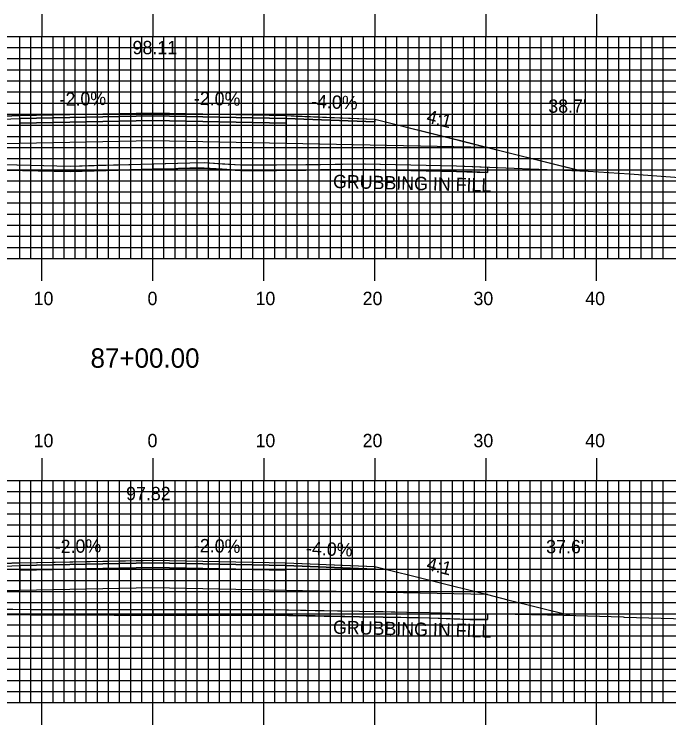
# Model space of a CAD drawing. Extents: x 1763759 to 1764102, y 442591 to 442811.
# Drawn here: x 1763911.8 to 1763970.8, y 442696.7 to 442760.7 of the extents above; entities that cross this region are included whole.
import ezdxf

# ---------------------------------------------------------------- set-up
doc = ezdxf.new("R2010")
doc.units = 0
for name, color, linetype in [('ANNOTATION', 7, 'Continuous'), ('D_Roadway_Centerline', 7, 'Continuous'), ('D_Roadway_Centerline_Text', 7, 'Continuous'), ('D_Roadway_Edge_Shoulder', 7, 'Continuous'), ('D_Roadway_Edge_TW', 7, 'Continuous'), ('D_Roadway_Pavement', 7, 'Continuous'), ('D_Roadway_SlopeLines', 7, 'Continuous'), ('D_Roadway_SubGrade', 7, 'Continuous'), ('D_Text_Standard', 7, 'Continuous'), ('GRUBBING IN FILL', 7, 'Continuous'), ('H_V ANNOTATION', 7, 'Continuous'), ('MAJOR', 7, 'Continuous'), ('MINOR', 7, 'Continuous'), ('S_Roadway_Centerline', 7, 'Continuous')]:
    doc.layers.add(name, color=color, linetype=linetype)

msp = doc.modelspace()

# ---------------------------------------------------------------- linework, layer by layer
at = {"layer": 'D_Roadway_Centerline'}
for points in [[(1763889.187, 442747.431), (1763889.189, 442747.432), (1763890.566, 442747.776), (1763894.144, 442748.67), (1763895.666, 442749.05), (1763904.277, 442751.203), (1763904.318, 442751.213), (1763912.318, 442751.533), (1763924.315, 442751.773), (1763924.318, 442751.773), (1763936.313, 442751.533), (1763936.319, 442751.533), (1763937.226, 442751.497), (1763944.314, 442751.213), (1763944.319, 442751.213), (1763951.794, 442749.345), (1763954.48, 442748.673), (1763954.493, 442748.67), (1763954.495, 442748.67), (1763954.995, 442748.544), (1763956.319, 442748.213), (1763961.352, 442746.955), (1763962.976, 442746.549)], [(1763890.259, 442707.415), (1763894.144, 442708.386), (1763897.914, 442709.329), (1763904.312, 442710.929), (1763904.319, 442710.93), (1763904.324, 442710.93), (1763907.002, 442711.038), (1763912.316, 442711.25), (1763912.319, 442711.25), (1763923.434, 442711.473), (1763924.318, 442711.49), (1763936.316, 442711.25), (1763936.318, 442711.25), (1763944.308, 442710.931), (1763944.319, 442710.93), (1763954.486, 442708.388), (1763954.492, 442708.386), (1763956.316, 442707.931), (1763956.319, 442707.93), (1763961.907, 442706.533), (1763961.911, 442706.532)]]:
    msp.add_lwpolyline(points, dxfattribs=at)
at = {"layer": 'D_Roadway_Edge_Shoulder'}
for points in [[(1763912.318, 442751.533), (1763904.318, 442751.213), (1763904.318, 442750.963), (1763912.318, 442751.283)], [(1763936.319, 442751.533), (1763944.319, 442751.213), (1763944.319, 442750.963), (1763936.319, 442751.283)], [(1763912.319, 442711.25), (1763904.319, 442710.93), (1763904.319, 442710.68), (1763912.319, 442711)], [(1763936.318, 442711.25), (1763944.319, 442710.93), (1763944.319, 442710.68), (1763936.318, 442711)]]:
    msp.add_lwpolyline(points, close=True, dxfattribs=at)
at = {"layer": 'D_Roadway_Edge_TW'}
for points in [[(1763912.318, 442751.283), (1763912.318, 442751.533), (1763924.318, 442751.773), (1763936.319, 442751.533), (1763936.319, 442751.283), (1763924.318, 442751.523)], [(1763936.319, 442751.533), (1763936.319, 442751.533), (1763936.319, 442751.283), (1763936.319, 442751.283)], [(1763912.319, 442711), (1763912.319, 442711.25), (1763924.318, 442711.49), (1763936.318, 442711.25), (1763936.318, 442711), (1763924.318, 442711.24)], [(1763936.318, 442711.25), (1763936.318, 442711.25), (1763936.318, 442711), (1763936.318, 442711)]]:
    msp.add_lwpolyline(points, close=True, dxfattribs=at)
at = {"layer": 'D_Roadway_Pavement'}
for points in [[(1763912.318, 442750.867), (1763912.318, 442751.283), (1763924.318, 442751.523), (1763936.319, 442751.283), (1763936.319, 442750.867), (1763924.318, 442751.107)], [(1763936.319, 442751.283), (1763936.319, 442751.283), (1763936.319, 442750.867), (1763936.319, 442750.867)], [(1763912.319, 442710.583), (1763912.319, 442711), (1763924.318, 442711.24), (1763936.318, 442711), (1763936.318, 442710.583), (1763924.318, 442710.823)], [(1763936.318, 442711), (1763936.318, 442711), (1763936.318, 442710.583), (1763936.318, 442710.583)]]:
    msp.add_lwpolyline(points, close=True, dxfattribs=at)
for points in [[(1763936.319, 442751.283), (1763936.319, 442750.867)], [(1763936.319, 442751.283), (1763936.319, 442750.867)], [(1763936.319, 442751.283), (1763936.319, 442750.867)], [(1763936.318, 442711), (1763936.318, 442710.583)], [(1763936.318, 442711), (1763936.318, 442710.583)], [(1763936.318, 442711), (1763936.318, 442710.583)]]:
    msp.add_lwpolyline(points, dxfattribs=at)
at = {"layer": 'D_Roadway_SlopeLines'}
for points in [[(1763944.319, 442751.213), (1763954.493, 442748.67), (1763956.319, 442748.213), (1763962.976, 442746.549)], [(1763944.319, 442710.93), (1763954.492, 442708.386), (1763956.319, 442707.93), (1763961.911, 442706.532)]]:
    msp.add_lwpolyline(points, dxfattribs=at)
at = {"layer": 'D_Roadway_SubGrade'}
for points in [[(1763904.318, 442750.963), (1763912.318, 442751.283), (1763912.318, 442750.867), (1763912.318, 442749.033), (1763894.144, 442748.67), (1763904.318, 442751.213)], [(1763912.318, 442749.033), (1763912.318, 442750.867), (1763924.318, 442751.107), (1763936.319, 442750.867), (1763936.319, 442749.033), (1763924.318, 442749.273)], [(1763936.319, 442750.867), (1763936.319, 442751.283), (1763944.319, 442750.963), (1763944.319, 442751.213), (1763954.493, 442748.67), (1763936.319, 442749.033)], [(1763936.319, 442750.867), (1763936.319, 442750.867), (1763936.319, 442749.033), (1763936.319, 442749.033)], [(1763904.319, 442710.68), (1763912.319, 442711), (1763912.319, 442710.583), (1763912.319, 442708.75), (1763894.144, 442708.386), (1763904.319, 442710.93)], [(1763912.319, 442708.75), (1763912.319, 442710.583), (1763924.318, 442710.823), (1763936.318, 442710.583), (1763936.318, 442708.75), (1763924.318, 442708.99)], [(1763936.318, 442710.583), (1763936.318, 442711), (1763944.319, 442710.68), (1763944.319, 442710.93), (1763954.492, 442708.386), (1763936.318, 442708.75)], [(1763936.318, 442710.583), (1763936.318, 442710.583), (1763936.318, 442708.75), (1763936.318, 442708.75)]]:
    msp.add_lwpolyline(points, close=True, dxfattribs=at)
at = {"layer": 'GRUBBING IN FILL'}
for p, q in [((1763954.493, 442746.899), (1763954.493, 442746.398)), ((1763954.492, 442706.645), (1763954.492, 442706.145))]:
    msp.add_line(p, q, dxfattribs=at)
for points in [[(1763894.144, 442747.474), (1763896.804, 442747.419), (1763900.618, 442747.34), (1763903.942, 442747.272), (1763906.489, 442747.219), (1763909.661, 442747.153), (1763913.259, 442747.074), (1763916.85, 442746.996), (1763919.345, 442747.064), (1763922.156, 442747.141), (1763924.319, 442747.201), (1763924.319, 442746.7), (1763922.255, 442746.644), (1763916.851, 442746.496), (1763909.658, 442746.653), (1763901.901, 442746.814), (1763894.144, 442746.974)], [(1763894.144, 442747.474), (1763896.804, 442747.419), (1763900.618, 442747.34), (1763903.942, 442747.272), (1763906.489, 442747.219), (1763909.661, 442747.153), (1763913.259, 442747.074), (1763916.85, 442746.996), (1763919.345, 442747.064), (1763922.156, 442747.141), (1763924.319, 442747.201), (1763924.319, 442746.7), (1763922.255, 442746.644), (1763916.851, 442746.496), (1763909.658, 442746.653), (1763901.901, 442746.814), (1763894.144, 442746.974)], [(1763924.319, 442747.201), (1763927.648, 442747.292), (1763928.95, 442747.308), (1763930.586, 442747.199), (1763932.221, 442747.091), (1763935.452, 442747.095), (1763939.424, 442747.138), (1763943.395, 442747.18), (1763947.571, 442747.097), (1763951.694, 442747.014), (1763954.493, 442746.899), (1763954.493, 442746.398), (1763953.085, 442746.456), (1763951.678, 442746.514), (1763947.56, 442746.597), (1763943.442, 442746.68), (1763939.426, 442746.638), (1763933.83, 442746.593), (1763932.205, 442746.591), (1763930.571, 442746.699), (1763928.936, 442746.807), (1763927.658, 442746.792), (1763926.628, 442746.764), (1763926.348, 442746.756), (1763924.319, 442746.7)], [(1763924.319, 442747.201), (1763927.648, 442747.292), (1763928.95, 442747.308), (1763930.586, 442747.199), (1763932.221, 442747.091), (1763935.452, 442747.095), (1763939.424, 442747.138), (1763943.395, 442747.18), (1763947.571, 442747.097), (1763951.694, 442747.014), (1763954.493, 442746.899), (1763954.493, 442746.398), (1763953.085, 442746.456), (1763951.678, 442746.514), (1763947.56, 442746.597), (1763943.442, 442746.68), (1763939.426, 442746.638), (1763933.83, 442746.593), (1763932.205, 442746.591), (1763930.571, 442746.699), (1763928.936, 442746.807), (1763927.658, 442746.792), (1763926.628, 442746.764), (1763926.348, 442746.756), (1763924.319, 442746.7)], [(1763894.144, 442707.484), (1763895.682, 442707.514), (1763899.02, 442707.435), (1763902.359, 442707.356), (1763906.253, 442707.223), (1763911.7, 442707.075), (1763913.254, 442707.06), (1763917.035, 442707.049), (1763920.815, 442707.039), (1763924.319, 442707.036), (1763924.319, 442706.536), (1763920.815, 442706.539), (1763917.035, 442706.549), (1763911.7, 442706.575), (1763906.253, 442706.723), (1763902.359, 442706.856), (1763899.02, 442706.935), (1763895.682, 442707.014), (1763894.144, 442706.984)], [(1763894.144, 442707.484), (1763895.682, 442707.514), (1763899.02, 442707.435), (1763902.359, 442707.356), (1763906.253, 442707.223), (1763911.7, 442707.075), (1763913.254, 442707.06), (1763917.035, 442707.049), (1763920.815, 442707.039), (1763924.319, 442707.036), (1763924.319, 442706.536), (1763920.815, 442706.539), (1763917.035, 442706.549), (1763911.7, 442706.575), (1763906.253, 442706.723), (1763902.359, 442706.856), (1763899.02, 442706.935), (1763895.682, 442707.014), (1763894.144, 442706.984)], [(1763924.319, 442707.036), (1763925.96, 442707.035), (1763931.106, 442707.032), (1763934.963, 442707.032), (1763938.955, 442706.965), (1763942.948, 442706.898), (1763945.078, 442706.86), (1763947.209, 442706.821), (1763949.3, 442706.788), (1763952.904, 442706.644), (1763954.492, 442706.645), (1763954.492, 442706.145), (1763952.904, 442706.144), (1763951.102, 442706.216), (1763948.255, 442706.305), (1763945.078, 442706.36), (1763942.948, 442706.398), (1763938.955, 442706.465), (1763934.963, 442706.532), (1763931.106, 442706.532), (1763925.96, 442706.535), (1763924.319, 442706.536)], [(1763924.319, 442707.036), (1763925.96, 442707.035), (1763931.106, 442707.032), (1763934.963, 442707.032), (1763938.955, 442706.965), (1763942.948, 442706.898), (1763945.078, 442706.86), (1763947.209, 442706.821), (1763949.3, 442706.788), (1763952.904, 442706.644), (1763954.492, 442706.645), (1763954.492, 442706.145), (1763952.904, 442706.144), (1763951.102, 442706.216), (1763948.255, 442706.305), (1763945.078, 442706.36), (1763942.948, 442706.398), (1763938.955, 442706.465), (1763934.963, 442706.532), (1763931.106, 442706.532), (1763925.96, 442706.535), (1763924.319, 442706.536)]]:
    msp.add_lwpolyline(points, close=True, dxfattribs=at)
for points in [[(1763894.144, 442746.974), (1763909.658, 442746.653), (1763916.851, 442746.496), (1763927.658, 442746.792), (1763928.936, 442746.807), (1763932.205, 442746.591), (1763935.455, 442746.595), (1763943.397, 442746.68), (1763943.442, 442746.68), (1763951.678, 442746.514), (1763954.493, 442746.398)], [(1763894.144, 442706.984), (1763895.682, 442707.014), (1763902.359, 442706.856), (1763910.147, 442706.59), (1763913.254, 442706.56), (1763920.815, 442706.539), (1763931.106, 442706.532), (1763934.963, 442706.532), (1763942.948, 442706.398), (1763947.209, 442706.321), (1763949.3, 442706.288), (1763952.904, 442706.144), (1763954.492, 442706.145)]]:
    msp.add_lwpolyline(points, dxfattribs=at)
at = {"layer": 'MAJOR'}
for p, q in [((1763914.319, 442760.669), (1763914.319, 442758.665)), ((1763924.319, 442760.669), (1763924.319, 442758.665)), ((1763934.319, 442760.669), (1763934.319, 442758.665)), ((1763944.319, 442760.669), (1763944.319, 442758.665)), ((1763954.319, 442760.669), (1763954.319, 442758.665)), ((1763964.319, 442760.669), (1763964.319, 442758.665)), ((1763784.319, 442758.665), (1764064.319, 442758.665)), ((1763784.319, 442758.665), (1764064.319, 442758.665)), ((1763914.319, 442738.665), (1763914.319, 442758.665)), ((1763924.319, 442738.665), (1763924.319, 442758.665)), ((1763934.319, 442738.665), (1763934.319, 442758.665)), ((1763944.319, 442738.665), (1763944.319, 442758.665)), ((1763954.319, 442738.665), (1763954.319, 442758.665)), ((1763964.319, 442738.665), (1763964.319, 442758.665)), ((1763784.319, 442753.665), (1764064.319, 442753.665)), ((1763784.319, 442748.665), (1764064.319, 442748.665)), ((1763784.319, 442743.665), (1764064.319, 442743.665)), ((1763784.319, 442738.665), (1764064.319, 442738.665)), ((1763784.319, 442738.665), (1764064.319, 442738.665)), ((1763914.319, 442736.661), (1763914.319, 442738.665)), ((1763924.319, 442736.661), (1763924.319, 442738.665)), ((1763934.319, 442736.661), (1763934.319, 442738.665)), ((1763944.319, 442736.661), (1763944.319, 442738.665)), ((1763954.319, 442736.661), (1763954.319, 442738.665)), ((1763964.319, 442736.661), (1763964.319, 442738.665)), ((1763914.319, 442720.669), (1763914.319, 442718.665)), ((1763924.319, 442720.669), (1763924.319, 442718.665)), ((1763934.319, 442720.669), (1763934.319, 442718.665)), ((1763944.319, 442720.669), (1763944.319, 442718.665)), ((1763954.319, 442720.669), (1763954.319, 442718.665)), ((1763964.319, 442720.669), (1763964.319, 442718.665)), ((1763784.319, 442718.665), (1764064.319, 442718.665)), ((1763784.319, 442718.665), (1764064.319, 442718.665)), ((1763914.319, 442698.665), (1763914.319, 442718.665)), ((1763924.319, 442698.665), (1763924.319, 442718.665)), ((1763934.319, 442698.665), (1763934.319, 442718.665)), ((1763944.319, 442698.665), (1763944.319, 442718.665)), ((1763954.319, 442698.665), (1763954.319, 442718.665)), ((1763964.319, 442698.665), (1763964.319, 442718.665)), ((1763784.319, 442713.665), (1764064.319, 442713.665)), ((1763784.319, 442708.665), (1764064.319, 442708.665)), ((1763784.319, 442703.665), (1764064.319, 442703.665)), ((1763784.319, 442698.665), (1764064.319, 442698.665)), ((1763784.319, 442698.665), (1764064.319, 442698.665)), ((1763914.319, 442696.661), (1763914.319, 442698.665)), ((1763924.319, 442696.661), (1763924.319, 442698.665)), ((1763934.319, 442696.661), (1763934.319, 442698.665)), ((1763944.319, 442696.661), (1763944.319, 442698.665)), ((1763954.319, 442696.661), (1763954.319, 442698.665)), ((1763964.319, 442696.661), (1763964.319, 442698.665))]:
    msp.add_line(p, q, dxfattribs=at)
at = {"layer": 'MINOR'}
for p, q in [((1763912.319, 442738.665), (1763912.319, 442758.665)), ((1763913.319, 442738.665), (1763913.319, 442758.665)), ((1763915.319, 442738.665), (1763915.319, 442758.665)), ((1763916.319, 442738.665), (1763916.319, 442758.665)), ((1763917.319, 442738.665), (1763917.319, 442758.665)), ((1763918.319, 442738.665), (1763918.319, 442758.665)), ((1763919.319, 442738.665), (1763919.319, 442758.665)), ((1763920.319, 442738.665), (1763920.319, 442758.665)), ((1763921.319, 442738.665), (1763921.319, 442758.665)), ((1763922.319, 442738.665), (1763922.319, 442758.665)), ((1763923.319, 442738.665), (1763923.319, 442758.665)), ((1763925.319, 442738.665), (1763925.319, 442758.665)), ((1763926.319, 442738.665), (1763926.319, 442758.665)), ((1763927.319, 442738.665), (1763927.319, 442758.665)), ((1763928.319, 442738.665), (1763928.319, 442758.665)), ((1763929.319, 442738.665), (1763929.319, 442758.665)), ((1763930.319, 442738.665), (1763930.319, 442758.665)), ((1763931.319, 442738.665), (1763931.319, 442758.665)), ((1763932.319, 442738.665), (1763932.319, 442758.665)), ((1763933.319, 442738.665), (1763933.319, 442758.665)), ((1763935.319, 442738.665), (1763935.319, 442758.665)), ((1763936.319, 442738.665), (1763936.319, 442758.665)), ((1763937.319, 442738.665), (1763937.319, 442758.665)), ((1763938.319, 442738.665), (1763938.319, 442758.665)), ((1763939.319, 442738.665), (1763939.319, 442758.665)), ((1763940.319, 442738.665), (1763940.319, 442758.665)), ((1763941.319, 442738.665), (1763941.319, 442758.665)), ((1763942.319, 442738.665), (1763942.319, 442758.665)), ((1763943.319, 442738.665), (1763943.319, 442758.665)), ((1763945.319, 442738.665), (1763945.319, 442758.665)), ((1763946.319, 442738.665), (1763946.319, 442758.665)), ((1763947.319, 442738.665), (1763947.319, 442758.665)), ((1763948.319, 442738.665), (1763948.319, 442758.665)), ((1763949.319, 442738.665), (1763949.319, 442758.665)), ((1763950.319, 442738.665), (1763950.319, 442758.665)), ((1763951.319, 442738.665), (1763951.319, 442758.665)), ((1763952.319, 442738.665), (1763952.319, 442758.665)), ((1763953.319, 442738.665), (1763953.319, 442758.665)), ((1763955.319, 442738.665), (1763955.319, 442758.665)), ((1763956.319, 442738.665), (1763956.319, 442758.665)), ((1763957.319, 442738.665), (1763957.319, 442758.665)), ((1763958.319, 442738.665), (1763958.319, 442758.665)), ((1763959.319, 442738.665), (1763959.319, 442758.665)), ((1763960.319, 442738.665), (1763960.319, 442758.665)), ((1763961.319, 442738.665), (1763961.319, 442758.665)), ((1763962.319, 442738.665), (1763962.319, 442758.665)), ((1763963.319, 442738.665), (1763963.319, 442758.665)), ((1763965.319, 442738.665), (1763965.319, 442758.665)), ((1763966.319, 442738.665), (1763966.319, 442758.665)), ((1763967.319, 442738.665), (1763967.319, 442758.665)), ((1763968.319, 442738.665), (1763968.319, 442758.665)), ((1763969.319, 442738.665), (1763969.319, 442758.665)), ((1763970.319, 442738.665), (1763970.319, 442758.665)), ((1763784.319, 442757.665), (1764064.319, 442757.665)), ((1763784.319, 442756.665), (1764064.319, 442756.665)), ((1763784.319, 442755.665), (1764064.319, 442755.665)), ((1763784.319, 442754.665), (1764064.319, 442754.665)), ((1763784.319, 442752.665), (1764064.319, 442752.665)), ((1763784.319, 442751.665), (1764064.319, 442751.665)), ((1763784.319, 442750.665), (1764064.319, 442750.665)), ((1763784.319, 442749.665), (1764064.319, 442749.665)), ((1763784.319, 442747.665), (1764064.319, 442747.665)), ((1763784.319, 442746.665), (1764064.319, 442746.665)), ((1763784.319, 442745.665), (1764064.319, 442745.665)), ((1763784.319, 442744.665), (1764064.319, 442744.665)), ((1763784.319, 442742.665), (1764064.319, 442742.665)), ((1763784.319, 442741.665), (1764064.319, 442741.665)), ((1763784.319, 442740.665), (1764064.319, 442740.665)), ((1763784.319, 442739.665), (1764064.319, 442739.665)), ((1763912.319, 442698.665), (1763912.319, 442718.665)), ((1763913.319, 442698.665), (1763913.319, 442718.665)), ((1763915.319, 442698.665), (1763915.319, 442718.665)), ((1763916.319, 442698.665), (1763916.319, 442718.665)), ((1763917.319, 442698.665), (1763917.319, 442718.665)), ((1763918.319, 442698.665), (1763918.319, 442718.665)), ((1763919.319, 442698.665), (1763919.319, 442718.665)), ((1763920.319, 442698.665), (1763920.319, 442718.665)), ((1763921.319, 442698.665), (1763921.319, 442718.665)), ((1763922.319, 442698.665), (1763922.319, 442718.665)), ((1763923.319, 442698.665), (1763923.319, 442718.665)), ((1763925.319, 442698.665), (1763925.319, 442718.665)), ((1763926.319, 442698.665), (1763926.319, 442718.665)), ((1763927.319, 442698.665), (1763927.319, 442718.665)), ((1763928.319, 442698.665), (1763928.319, 442718.665)), ((1763929.319, 442698.665), (1763929.319, 442718.665)), ((1763930.319, 442698.665), (1763930.319, 442718.665)), ((1763931.319, 442698.665), (1763931.319, 442718.665)), ((1763932.319, 442698.665), (1763932.319, 442718.665)), ((1763933.319, 442698.665), (1763933.319, 442718.665)), ((1763935.319, 442698.665), (1763935.319, 442718.665)), ((1763936.319, 442698.665), (1763936.319, 442718.665)), ((1763937.319, 442698.665), (1763937.319, 442718.665)), ((1763938.319, 442698.665), (1763938.319, 442718.665)), ((1763939.319, 442698.665), (1763939.319, 442718.665)), ((1763940.319, 442698.665), (1763940.319, 442718.665)), ((1763941.319, 442698.665), (1763941.319, 442718.665)), ((1763942.319, 442698.665), (1763942.319, 442718.665)), ((1763943.319, 442698.665), (1763943.319, 442718.665)), ((1763945.319, 442698.665), (1763945.319, 442718.665)), ((1763946.319, 442698.665), (1763946.319, 442718.665)), ((1763947.319, 442698.665), (1763947.319, 442718.665)), ((1763948.319, 442698.665), (1763948.319, 442718.665)), ((1763949.319, 442698.665), (1763949.319, 442718.665)), ((1763950.319, 442698.665), (1763950.319, 442718.665)), ((1763951.319, 442698.665), (1763951.319, 442718.665)), ((1763952.319, 442698.665), (1763952.319, 442718.665)), ((1763953.319, 442698.665), (1763953.319, 442718.665)), ((1763955.319, 442698.665), (1763955.319, 442718.665)), ((1763956.319, 442698.665), (1763956.319, 442718.665)), ((1763957.319, 442698.665), (1763957.319, 442718.665)), ((1763958.319, 442698.665), (1763958.319, 442718.665)), ((1763959.319, 442698.665), (1763959.319, 442718.665)), ((1763960.319, 442698.665), (1763960.319, 442718.665)), ((1763961.319, 442698.665), (1763961.319, 442718.665)), ((1763962.319, 442698.665), (1763962.319, 442718.665)), ((1763963.319, 442698.665), (1763963.319, 442718.665)), ((1763965.319, 442698.665), (1763965.319, 442718.665)), ((1763966.319, 442698.665), (1763966.319, 442718.665)), ((1763967.319, 442698.665), (1763967.319, 442718.665)), ((1763968.319, 442698.665), (1763968.319, 442718.665)), ((1763969.319, 442698.665), (1763969.319, 442718.665)), ((1763970.319, 442698.665), (1763970.319, 442718.665)), ((1763784.319, 442717.665), (1764064.319, 442717.665)), ((1763784.319, 442716.665), (1764064.319, 442716.665)), ((1763784.319, 442715.665), (1764064.319, 442715.665)), ((1763784.319, 442714.665), (1764064.319, 442714.665)), ((1763784.319, 442712.665), (1764064.319, 442712.665)), ((1763784.319, 442711.665), (1764064.319, 442711.665)), ((1763784.319, 442710.665), (1764064.319, 442710.665)), ((1763784.319, 442709.665), (1764064.319, 442709.665)), ((1763784.319, 442707.665), (1764064.319, 442707.665)), ((1763784.319, 442706.665), (1764064.319, 442706.665)), ((1763784.319, 442705.665), (1764064.319, 442705.665)), ((1763784.319, 442704.665), (1764064.319, 442704.665)), ((1763784.319, 442702.665), (1764064.319, 442702.665)), ((1763784.319, 442701.665), (1764064.319, 442701.665)), ((1763784.319, 442700.665), (1764064.319, 442700.665)), ((1763784.319, 442699.665), (1764064.319, 442699.665))]:
    msp.add_line(p, q, dxfattribs=at)
at = {"layer": 'S_Roadway_Centerline'}
for points in [[(1763854.828, 442746.006), (1763867.386, 442747.029), (1763873.489, 442747.092), (1763879.439, 442747.107), (1763891.836, 442747.519), (1763892.337, 442747.514), (1763893.166, 442747.494), (1763909.668, 442747.153), (1763916.85, 442746.996), (1763927.648, 442747.292), (1763928.95, 442747.308), (1763932.221, 442747.091), (1763935.452, 442747.095), (1763943.395, 442747.18), (1763943.448, 442747.18), (1763951.694, 442747.014), (1763963.571, 442746.525), (1763967.273, 442746.276), (1763975.063, 442745.732)], [(1763860.214, 442706.945), (1763877.726, 442707.246), (1763891.289, 442707.429), (1763895.682, 442707.514), (1763902.359, 442707.356), (1763910.147, 442707.09), (1763913.254, 442707.06), (1763920.815, 442707.039), (1763931.106, 442707.032), (1763934.963, 442707.032), (1763942.948, 442706.898), (1763947.209, 442706.821), (1763949.3, 442706.788), (1763952.904, 442706.644), (1763955.503, 442706.646), (1763961.357, 442706.549), (1763966.71, 442706.383), (1763966.789, 442706.364), (1763983.488, 442705.893)]]:
    msp.add_lwpolyline(points, dxfattribs=at)

# ---------------------------------------------------------------- texts
at = {"layer": 'ANNOTATION'}
for s, rotation, p in [('-2.0%', 1.14574, (1763915.923, 442752.406)), ('-2.0%', 358.85426, (1763928.002, 442752.5)), ('-4.0%', 357.70933, (1763938.562, 442752.245)), ('4:1', 345.9664, (1763948.905, 442750.928)), ('-2.0%', 1.14583, (1763915.483, 442712.114)), ('-2.0%', 358.85426, (1763928.003, 442712.217)), ('-4.0%', 357.70948, (1763938.105, 442711.98)), ('4:1', 345.96056, (1763948.908, 442710.644))]:
    msp.add_text(s, height=1.2, rotation=rotation, dxfattribs=at).set_placement(p)
at = {"layer": 'D_Roadway_Centerline'}
for s, p in [('C', (1763924.313, 442751.773)), ('L', (1763924.318, 442751.766)), ('C', (1763924.313, 442711.49)), ('L', (1763924.318, 442711.483))]:
    msp.add_text(s, height=0.0146, dxfattribs=at).set_placement(p)
at = {"layer": 'D_Roadway_Centerline_Text'}
for s, p in [('98.11', (1763922.489, 442757.067)), ('97.82', (1763921.905, 442716.892))]:
    msp.add_text(s, height=1.2, dxfattribs=at).set_placement(p)
at = {"layer": 'D_Text_Standard'}
for s, p in [("38.7'", (1763959.961, 442751.793)), ("37.6'", (1763959.768, 442712.109))]:
    msp.add_text(s, height=1.2, dxfattribs=at).set_placement(p)
at = {"layer": 'GRUBBING IN FILL'}
for p in [(1763940.544, 442745.018), (1763940.544, 442704.862)]:
    msp.add_text('GRUBBING IN FILL', height=1.2, rotation=358.58067, dxfattribs=at).set_placement(p)
at = {"layer": 'H_V ANNOTATION'}
for s, height, p in [('10', 1.2, (1763913.569, 442734.465)), ('0', 1.2, (1763923.837, 442734.465)), ('10', 1.2, (1763933.569, 442734.465)), ('20', 1.2, (1763943.227, 442734.465)), ('30', 1.2, (1763953.216, 442734.465)), ('40', 1.2, (1763963.291, 442734.465)), ('87+00.00', 1.75, (1763918.7, 442728.821)), ('10', 1.2, (1763913.569, 442721.665)), ('0', 1.2, (1763923.837, 442721.665)), ('10', 1.2, (1763933.569, 442721.665)), ('20', 1.2, (1763943.227, 442721.665)), ('30', 1.2, (1763953.216, 442721.665)), ('40', 1.2, (1763963.291, 442721.665))]:
    msp.add_text(s, height=height, dxfattribs=at).set_placement(p)

doc.saveas('drawing.dxf')
